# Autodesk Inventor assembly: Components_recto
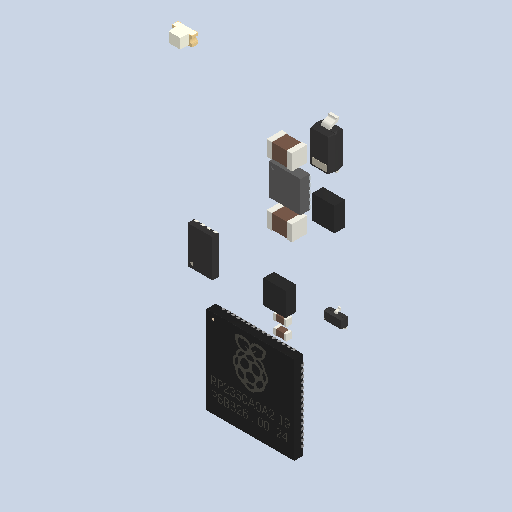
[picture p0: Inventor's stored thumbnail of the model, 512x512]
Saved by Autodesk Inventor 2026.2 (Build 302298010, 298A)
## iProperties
Created: 2026-10
Part Number: Components_recto
Document SubType Name: Assembly
Designer: mel
Author: mel
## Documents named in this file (13)
- D:\travail\année 2026-2027\1 sti2d IT\poubelle à verre\raspberry-pico-2-microcontroller-rp2350-1.snapshot.5\raspberry_pico_2\raspberry_pico_2\Components_recto.iam
- D:\travail\année 2026-2027\1 sti2d IT\poubelle à verre\raspberry-pico-2-microcontroller-rp2350-1.snapshot.5\raspberry_pico_2\raspberry_pico_2\QFN60-RP2350A.iam
- D:\travail\année 2026-2027\1 sti2d IT\poubelle à verre\raspberry-pico-2-microcontroller-rp2350-1.snapshot.5\raspberry_pico_2\raspberry_pico_2\D_SOD-123.ipt
- D:\travail\année 2026-2027\1 sti2d IT\poubelle à verre\raspberry-pico-2-microcontroller-rp2350-1.snapshot.5\raspberry_pico_2\raspberry_pico_2\RT6150B-33GQW.iam
- D:\travail\année 2026-2027\1 sti2d IT\poubelle à verre\raspberry-pico-2-microcontroller-rp2350-1.snapshot.5\raspberry_pico_2\raspberry_pico_2\self.ipt
- D:\travail\année 2026-2027\1 sti2d IT\poubelle à verre\raspberry-pico-2-microcontroller-rp2350-1.snapshot.5\raspberry_pico_2\raspberry_pico_2\C_0402_1005Metric.ipt
- D:\travail\année 2026-2027\1 sti2d IT\poubelle à verre\raspberry-pico-2-microcontroller-rp2350-1.snapshot.5\raspberry_pico_2\raspberry_pico_2\C_0805_2012Metric.ipt
- D:\travail\année 2026-2027\1 sti2d IT\poubelle à verre\raspberry-pico-2-microcontroller-rp2350-1.snapshot.5\raspberry_pico_2\raspberry_pico_2\C_0805_2012Metric001.ipt
- D:\travail\année 2026-2027\1 sti2d IT\poubelle à verre\raspberry-pico-2-microcontroller-rp2350-1.snapshot.5\raspberry_pico_2\raspberry_pico_2\C_0402_1005Metric001.ipt
- D:\travail\année 2026-2027\1 sti2d IT\poubelle à verre\raspberry-pico-2-microcontroller-rp2350-1.snapshot.5\raspberry_pico_2\raspberry_pico_2\Winbond_USON-8-1EP_3x2mm_P0.5mm_EP0.2x1.6mm.ipt
- D:\travail\année 2026-2027\1 sti2d IT\poubelle à verre\raspberry-pico-2-microcontroller-rp2350-1.snapshot.5\raspberry_pico_2\raspberry_pico_2\self001.ipt
- D:\travail\année 2026-2027\1 sti2d IT\poubelle à verre\raspberry-pico-2-microcontroller-rp2350-1.snapshot.5\raspberry_pico_2\raspberry_pico_2\LED_0603_1608Metric_Castellated.ipt
- D:\travail\année 2026-2027\1 sti2d IT\poubelle à verre\raspberry-pico-2-microcontroller-rp2350-1.snapshot.5\raspberry_pico_2\raspberry_pico_2\SOT-524.ipt
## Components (12 placed, 12 different names)
1. 2757 [sub-assembly]
2. 2758
3. 2772 [sub-assembly]
4. 2773
5. 2774
6. 2775
7. 2776
8. 2777
9. 2778
10. 2779
11. 2780
12. 2781
